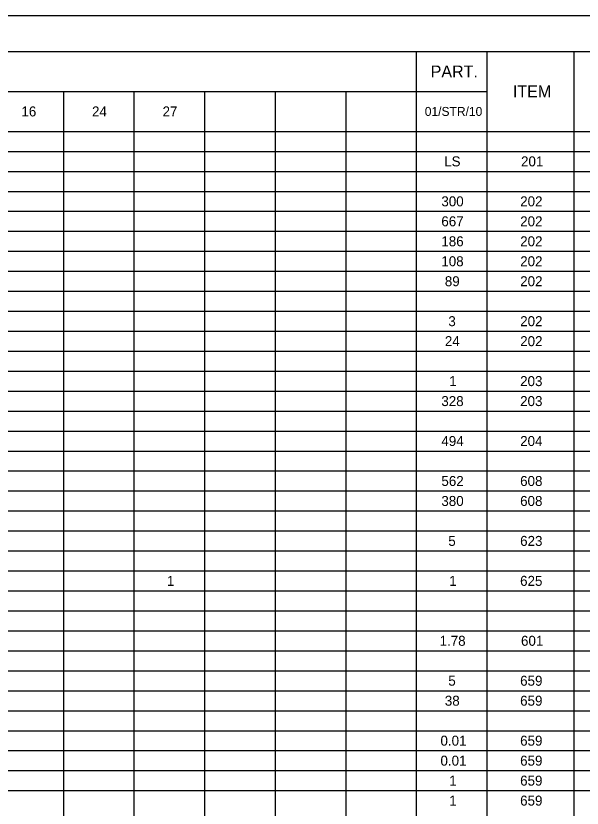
# Model space of a CAD drawing. Extents: x 0 to 34, y 0 to 22.
# Drawn here: x 8.74 to 16.67, y 10.89 to 22 of the extents above; entities that cross this region are included whole.
import ezdxf

# ---------------------------------------------------------------- set-up
doc = ezdxf.new("R2010")
doc.units = 0
for name, color, linetype in [('Default', 7, 'Continuous'), ('SH_Border', 7, 'Continuous'), ('SH_Cut_Line', 7, 'Continuous')]:
    doc.layers.add(name, color=color, linetype=linetype)

msp = doc.modelspace()

# ---------------------------------------------------------------- linework, layer by layer
at = {"layer": 'Default'}
for p, q in [((1.5, 21.5), (31.68951, 21.5)), ((14.3466, 21.5), (14.3466, 0.50075)), ((15.3348, 21.5), (15.3348, 0.50075)), ((16.55358, 21.5), (16.55358, 0.50075)), ((1.5, 20.94002), (15.3348, 20.94002)), ((9.4056, 20.94002), (9.4056, 0.50075)), ((10.3938, 20.94002), (10.3938, 0.50075)), ((11.382, 20.94002), (11.382, 0.50075)), ((12.3702, 20.94002), (12.3702, 0.50075)), ((13.3584, 20.94002), (13.3584, 0.50075)), ((1.5, 20.38004), (31.68951, 20.38004)), ((1.5, 20.10005), (31.68951, 20.10005)), ((1.5, 19.82006), (31.68951, 19.82006)), ((1.5, 19.54007), (31.68951, 19.54007)), ((1.5, 19.26008), (31.68951, 19.26008)), ((1.5, 18.98009), (31.68951, 18.98009)), ((1.5, 18.7001), (31.68951, 18.7001)), ((1.5, 18.42011), (31.68951, 18.42011)), ((1.5, 18.14012), (31.68951, 18.14012)), ((1.5, 17.86013), (31.68951, 17.86013)), ((1.5, 17.58014), (31.68951, 17.58014)), ((1.5, 17.30015), (31.68951, 17.30015)), ((1.5, 17.02016), (31.68951, 17.02016)), ((1.5, 16.74017), (31.68951, 16.74017)), ((1.5, 16.46018), (31.68951, 16.46018)), ((1.5, 16.18019), (31.68951, 16.18019)), ((1.5, 15.9002), (31.68951, 15.9002)), ((1.5, 15.62021), (31.68951, 15.62021)), ((1.5, 15.34022), (31.68951, 15.34022)), ((1.5, 15.06023), (31.68951, 15.06023)), ((1.5, 14.78024), (31.68951, 14.78024)), ((1.5, 14.50025), (31.68951, 14.50025)), ((1.5, 14.22026), (31.68951, 14.22026)), ((1.5, 13.94027), (31.68951, 13.94027)), ((1.5, 13.66028), (31.68951, 13.66028)), ((1.5, 13.38029), (31.68951, 13.38029)), ((1.5, 13.1003), (31.68951, 13.1003)), ((1.5, 12.82031), (31.68951, 12.82031)), ((1.5, 12.54032), (31.68951, 12.54032)), ((1.5, 12.26033), (31.68951, 12.26033)), ((1.5, 11.98034), (31.68951, 11.98034)), ((1.5, 11.70035), (31.68951, 11.70035)), ((1.5, 11.42036), (31.68951, 11.42036)), ((1.5, 11.14037), (31.68951, 11.14037))]:
    msp.add_line(p, q, dxfattribs=at)
at = {"layer": 'SH_Border'}
msp.add_lwpolyline([(1.5, 21.5), (33.5, 21.5), (33.5, 0.5), (1.5, 0.5)], close=True, dxfattribs=at)
at = {"layer": 'SH_Cut_Line'}
msp.add_lwpolyline([(0, 0), (34, 0), (34, 22), (0, 22)], close=True, dxfattribs=at)

# ---------------------------------------------------------------- texts
at = {"layer": 'Default'}
for s, height, p in [('PART.', 0.168, (14.548557, 21.13601)), ('ITEM', 0.168, (15.699815, 20.85602)), ('16', 0.14, (8.817624, 20.59003)), ('24', 0.14, (9.806112, 20.59003)), ('27', 0.14, (10.794024, 20.59003)), ('01/STR/10', 0.126, (14.465884, 20.59703)), ('LS', 0.14, (14.737653, 19.890055)), ('201', 0.14, (15.81358, 19.890055)), ('300', 0.14, (14.698134, 19.330075)), ('202', 0.14, (15.802056, 19.330075)), ('667', 0.14, (14.697894, 19.050085)), ('202', 0.14, (15.802056, 19.050085)), ('186', 0.14, (14.697894, 18.770095)), ('202', 0.14, (15.802056, 18.770095)), ('108', 0.14, (14.697798, 18.490105)), ('202', 0.14, (15.802056, 18.490105)), ('89', 0.14, (14.746728, 18.210115)), ('202', 0.14, (15.802056, 18.210115)), ('3', 0.14, (14.795755, 17.650135)), ('202', 0.14, (15.802056, 17.650135)), ('24', 0.14, (14.747112, 17.370145)), ('202', 0.14, (15.802056, 17.370145)), ('1', 0.14, (14.807952, 16.810165)), ('203', 0.14, (15.801384, 16.810165)), ('328', 0.14, (14.697798, 16.530175)), ('203', 0.14, (15.801384, 16.530175)), ('494', 0.14, (14.698182, 15.970195)), ('204', 0.14, (15.801672, 15.970195)), ('562', 0.14, (14.698566, 15.410215)), ('608', 0.14, (15.801288, 15.410215)), ('380', 0.14, (14.698134, 15.130225)), ('608', 0.14, (15.801288, 15.130225)), ('5', 0.14, (14.795275, 14.570245)), ('623', 0.14, (15.801384, 14.570245)), ('1', 0.14, (10.855152, 14.010265)), ('1', 0.14, (14.807952, 14.010265)), ('625', 0.14, (15.800903, 14.010265)), ('1.78', 0.14, (14.673356, 13.170295)), ('601', 0.14, (15.81358, 13.170295)), ('5', 0.14, (14.795275, 12.610315)), ('659', 0.14, (15.801288, 12.610315)), ('38', 0.14, (14.746728, 12.330325)), ('659', 0.14, (15.801288, 12.330325)), ('0.01', 0.14, (14.685649, 11.770345)), ('659', 0.14, (15.801288, 11.770345)), ('0.01', 0.14, (14.685649, 11.490355)), ('659', 0.14, (15.801288, 11.490355)), ('1', 0.14, (14.807952, 11.210365)), ('659', 0.14, (15.801288, 11.210365)), ('1', 0.14, (14.807952, 10.930375)), ('659', 0.14, (15.801288, 10.930375))]:
    msp.add_text(s, height=height, dxfattribs=at).set_placement(p)

doc.saveas('drawing.dxf')
